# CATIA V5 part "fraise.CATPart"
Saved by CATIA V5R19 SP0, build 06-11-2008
Part number: fraise
Bounding box of the stored display mesh (mm): x -5 to 5, y 0 to 30, z -5 to 5
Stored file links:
  C:\Users\Alex\IFMA\2A\IAO\Modélisation\fraise.CATPart
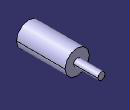
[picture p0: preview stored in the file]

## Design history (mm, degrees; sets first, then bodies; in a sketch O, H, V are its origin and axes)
Body1 (main body)
  Sketch1 on zx-plane, origin (0, 0, 0), H (-1, 0, 0), V (0, 0, 1)
    circle A1 centre (0, 0) radius 5
    radius A1 = 5
  Pad1: profile Sketch1, direction (0, 1, 0), length 20
  Sketch2 on end face of Pad1, origin (0, 20, 0), H (-1, 0, 0), V (0, 0, 1)
    circle A1 centre (0, 0) radius 1.5
    radius A1 = 1.5
  Pad2: profile Sketch2, direction (0, 1, 0), length 10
